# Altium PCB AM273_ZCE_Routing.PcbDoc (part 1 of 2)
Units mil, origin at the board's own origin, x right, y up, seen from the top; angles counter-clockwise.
Board outline 825 x 1150 mil, 4 copper layers (Top Layer, GND, Power, Bottom Layer), stack 60.63 mil thick; 37 components, 157 nets, 353 pads, 168 vias.
Unrouted connection lines stored in the file: 5.
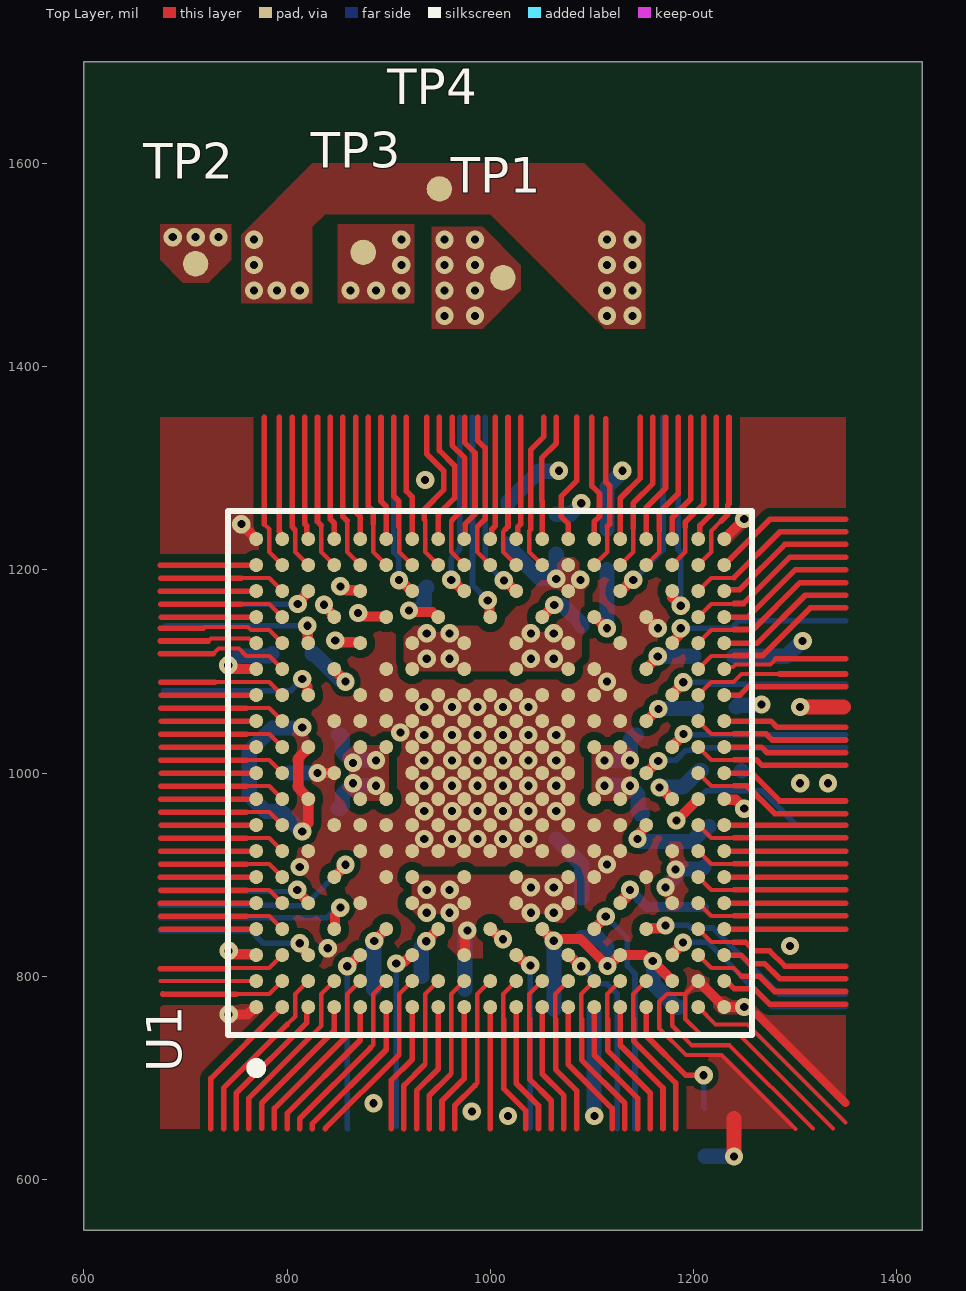
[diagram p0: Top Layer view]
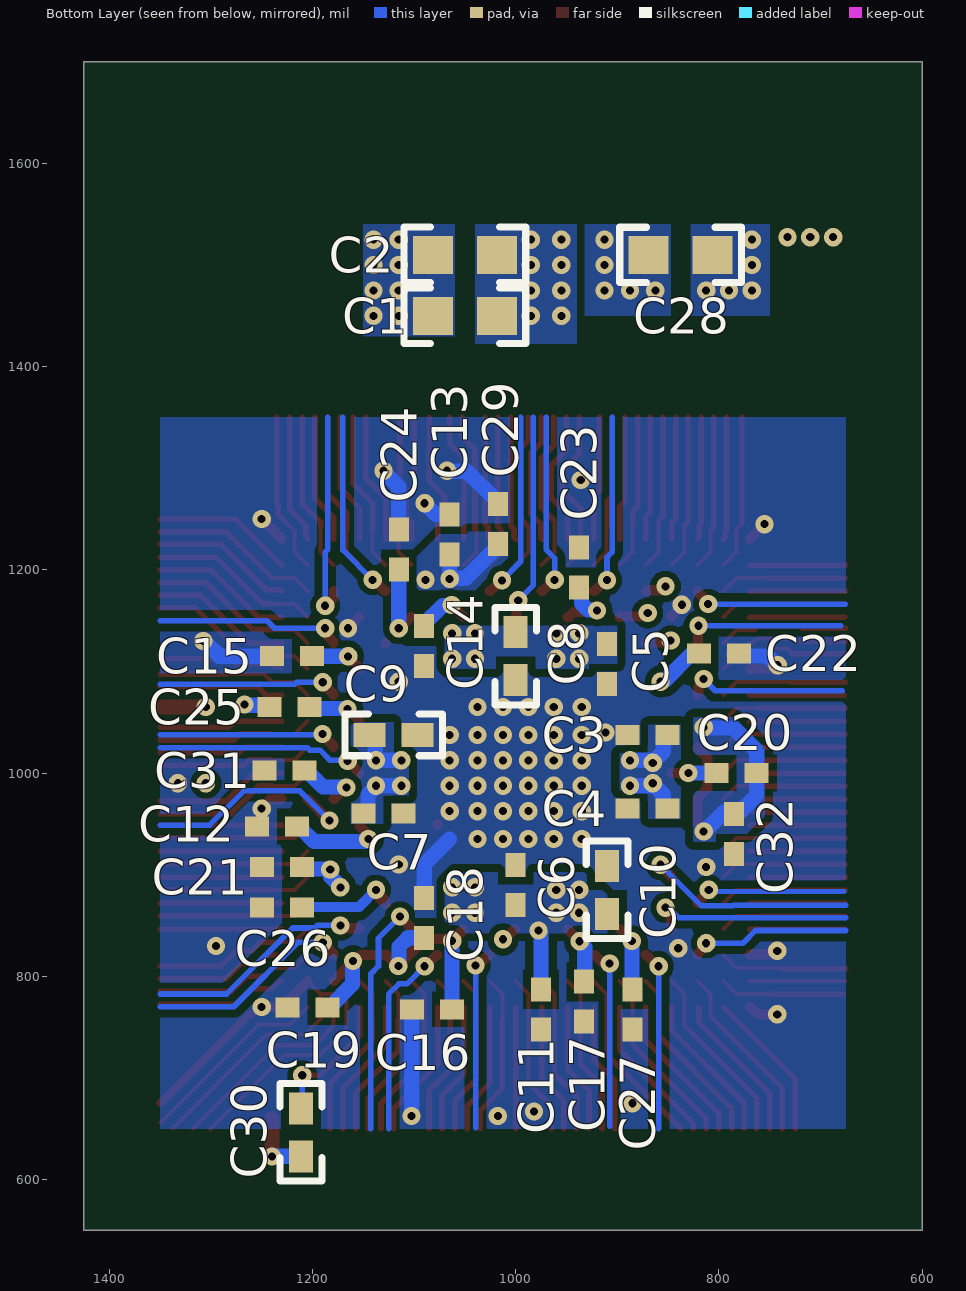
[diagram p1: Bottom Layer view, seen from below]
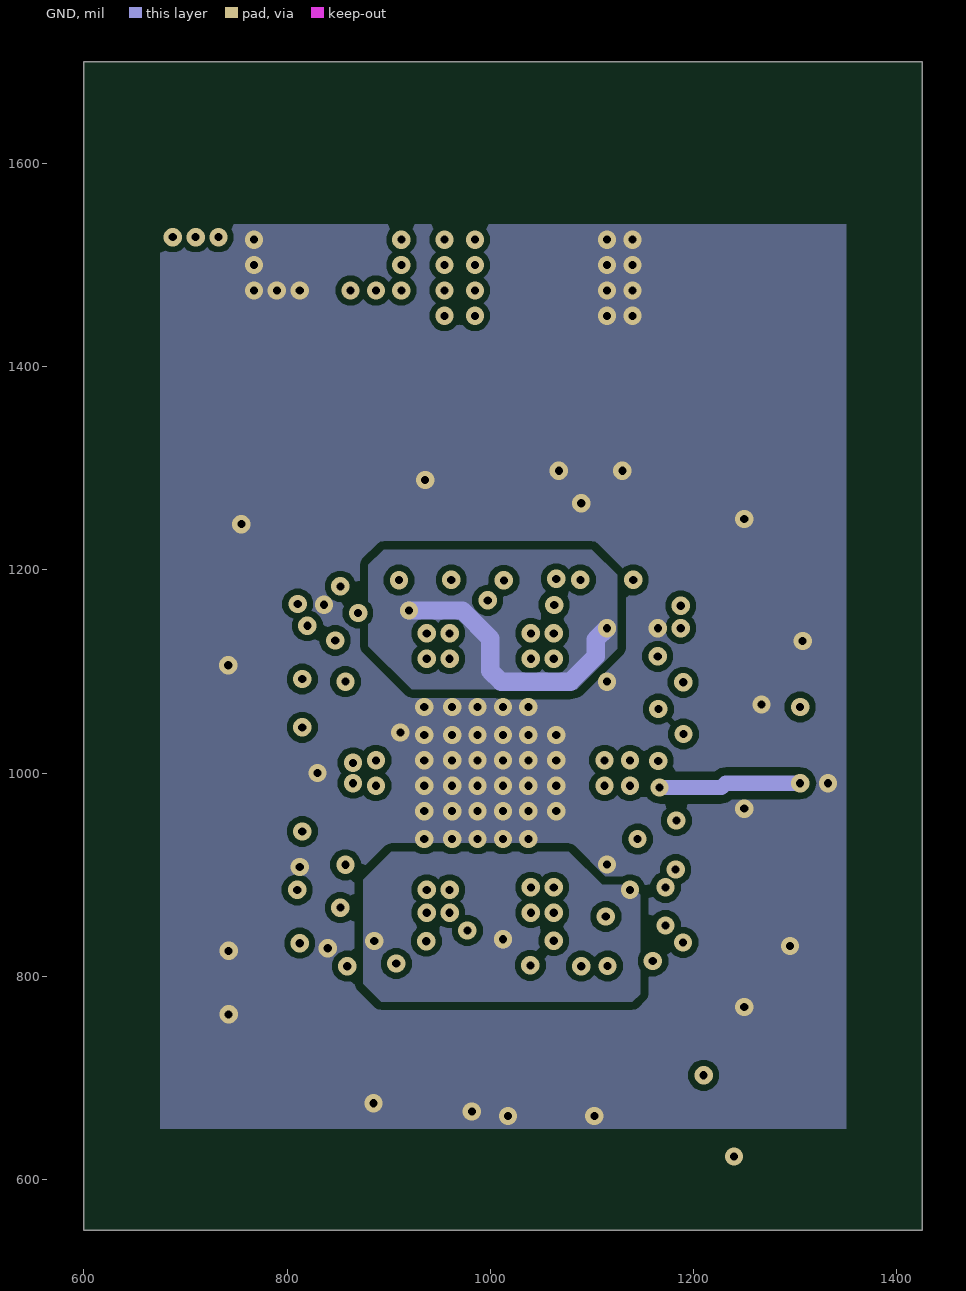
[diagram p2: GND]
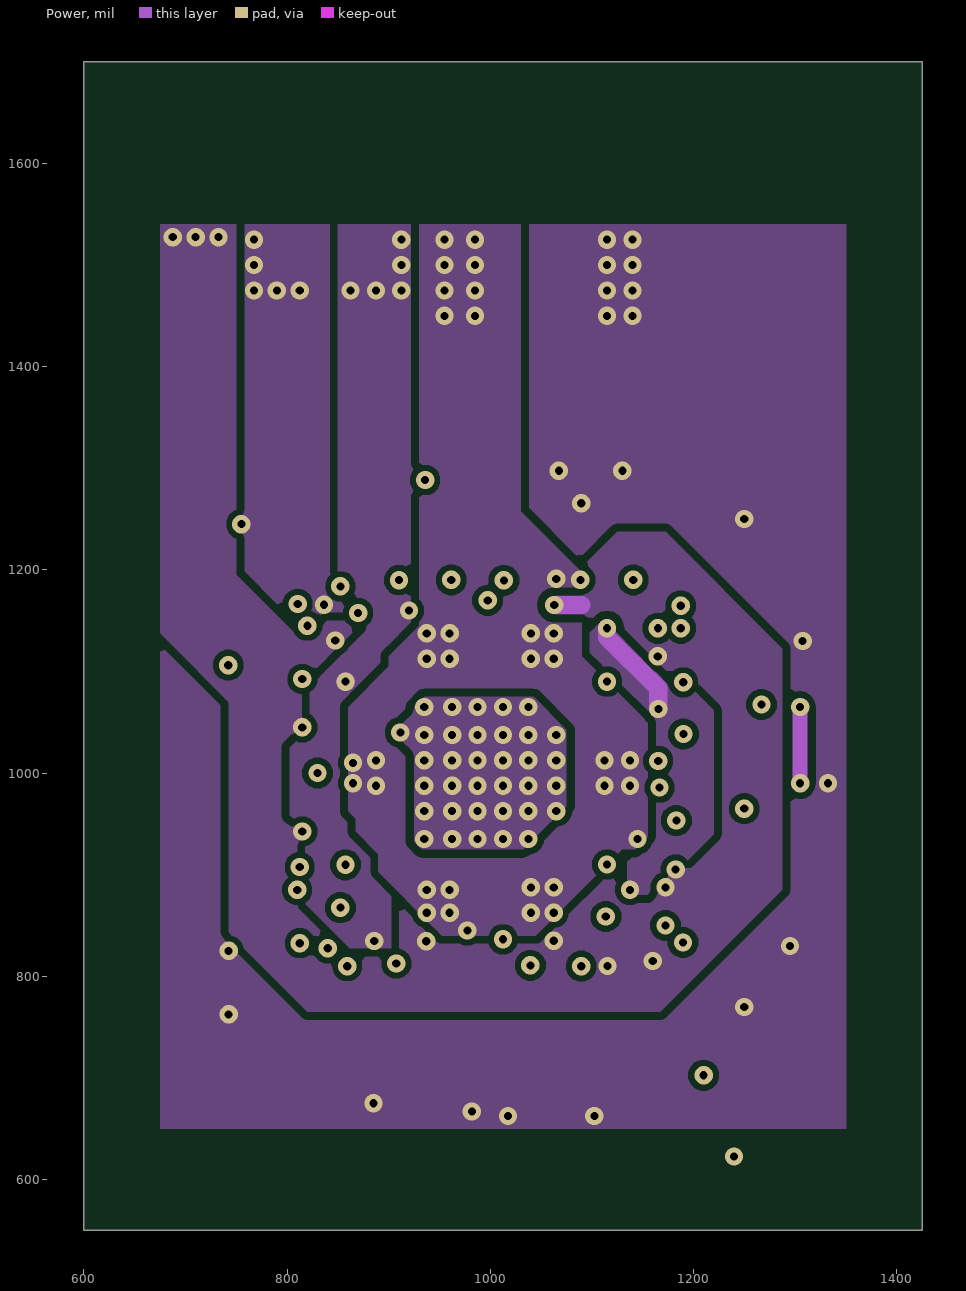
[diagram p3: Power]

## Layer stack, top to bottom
Top Solder: solder mask 0.394, Solder Resist, Dk 3.3
Top Layer: signal copper 1.378
Dielectric 1: prepreg 3.937, FR-4 High Tg, Dk 4.3
GND: signal copper 1.378
Dielectric 2: core 47.244, FR-4 High Tg, Dk 4.3
Power: signal copper 1.378
Dielectric 3: prepreg 3.937, FR-4 High Tg, Dk 4.3
Bottom Layer: signal copper 1.378
Bottom Solder: solder mask 0.394, Solder Resist, Dk 3.3

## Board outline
600,550 600,1700 1425,1700 1425,550

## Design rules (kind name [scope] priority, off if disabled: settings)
AcuteAngle [All] p1: minimum=4.50000000000000E+0001 checktracksonly=FALSE
AssemblyTestPointUsage [All] p1: valid=2
BoardOutlineClearance BoardOutlineClearance_MountingHoles [OnCopper and InComponentClass('Mounting Holes')] p1: gap=39.37 ignorepadtopadclearanceinfootprint=FALSE
BoardOutlineClearance BoardOutlineClearance_Poly [OnCopper and IsPoly] p2: gap=25 ignorepadtopadclearanceinfootprint=FALSE
BoardOutlineClearance [OnCopper and Not InComponentClass('Logo') and not InComponentClass('FiducialMark') and not InRegion(1000,500,4000,800) and not InPoly] p3: gap=40 ignorepadtopadclearanceinfootprint=FALSE
Clearance Clearance_Keepouts [((IsTrack Or IsArc) And Not InPoly) And IsFree and IsKeepOut vs ((IsTrack Or IsArc) And Not InPoly) And IsFree and IsKeepOut] p1: gap=0 ignorepadtopadclearanceinfootprint=FALSE
Clearance Clearance_Poly [InPolygon] p2: gap=10 ignorepadtopadclearanceinfootprint=TRUE except(6: Via-Fill Via-Poly Via-Region; 8: Arc-Fill Arc-Poly Arc-Region Track-Fill Track-Poly Track-Region SMDPad-Fill SMDPad-Poly SMDPad-Region Fill-Fill Fill-Poly Fill-Region Poly-Poly Poly-Region Region-Region; 12: THPad-Fill THPad-Poly THPad-Region)
Clearance Clearance_FiducialMark [IsKeepOut and InComponentClass('FiducialMark') vs IsPad and InComponentClass('FiducialMark')] p3: gap=0 ignorepadtopadclearanceinfootprint=FALSE
Clearance [All] p4: gap=4 ignorepadtopadclearanceinfootprint=TRUE except(3.52: SMDPad-Via; 3.9: Arc-SMDPad Track-SMDPad; 7.87: Arc-THPad Arc-Text Arc-Hole Track-THPad Track-Text Track-Hole SMDPad-THPad SMDPad-Text SMDPad-Hole THPad-THPad THPad-Via THPad-Fill THPad-Poly THPad-Region THPad-Text THPad-Hole Via-Text Via-Hole Fill-Text Fill-Hole Poly-Text Poly-Hole Region-Text Region-Hole Text-Text Text-Hole)
ComponentClearance ComponentClearance_MountingHoles_FiducialMarks [InComponentClass('Mounting Holes') vs InComponentClass('FiducialMark')] p1: gap=50 collisioncheckmode=3 verticalgap=10 showdistances=FALSE
ComponentClearance ComponentClearance_Shunt [InComponentClass('Header') vs InComponentClass('Shunt')] p2: gap=0 collisioncheckmode=3 verticalgap=0 showdistances=FALSE
ComponentClearance ComponentClearance_Logo [InComponentClass('Logo')] p3: gap=30 collisioncheckmode=3 verticalgap=10 showdistances=FALSE
ComponentClearance ComponentClearance_ScrewToNut [(HasFootprint('NY PMS 440 0025 PH')) vs (HasFootprint('Keystone_1902C'))] p4: gap=5 collisioncheckmode=3 verticalgap=10 showdistances=FALSE
ComponentClearance ComponentClearance_MountingHoles [InComponentClass('Mounting Holes')] p5: gap=100 collisioncheckmode=3 verticalgap=100000 showdistances=FALSE
ComponentClearance ComponentClearance_SmallPassives [HasFootprint('0201*') or HasFootprint('0402*') or HasFootprint('0508') or HasFootprint('0603*') or HasFootprint('0612') or HasFootprint('0805*') or HasFootprint('0815*') or HasFootprint('0830*') or HasFootprint('1206*') or HasFootprint('1210*') or HasFootprint('1808*') or HasFootprint('1812*') or HasFootprint('1825*') or HasFootprint('2010*') or HasFootprint('2220*') or HasFootprint('2225*') or HasFootprint('2512*') or HasFootprint('2728*') or HasFootprint('3518*') vs HasFootprint('0201*') or HasFootprint('0402*') or HasFootprint('0508') or HasFootprint('0603*') or HasFootprint('0612') or HasFootprint('0805*') or HasFootprint('0815*') or HasFootprint('0830*') or HasFootprint('1206*') or HasFootprint('1210*') or HasFootprint('1808*') or HasFootprint('1812*') or HasFootprint('1825*') or HasFootprint('2010*') or HasFootprint('2220*') or HasFootprint('2225*') or HasFootprint('2512*') or HasFootprint('2728*') or HasFootprint('3518*')] p6: gap=14.96 collisioncheckmode=3 verticalgap=10 showdistances=FALSE
ComponentClearance ComponentClearance_THtoSMT [IsThruComponent vs IsSMTComponent] p7: gap=30 collisioncheckmode=3 verticalgap=30 showdistances=FALSE
ComponentClearance ComponentClearance_THtoTH [IsThruComponent vs IsThruComponent] p8: gap=20 collisioncheckmode=3 verticalgap=30 showdistances=FALSE
ComponentClearance [All] p9: gap=20 collisioncheckmode=3 verticalgap=10 showdistances=FALSE
DiffPairsRouting [All] p1: maxlimit=100 minlimit=10 mostfreqgap=10 toplayer_minwidth=15 toplayer_maxwidth=15 toplayer_prefwidth=15 midlayer1_minwidth=15 midlayer1_maxwidth=15 midlayer1_prefwidth=15 midlayer4_minwidth=15 midlayer4_maxwidth=15 midlayer4_prefwidth=15 bottomlayer_minwidth=15 bottomlayer_maxwidth=15 bottomlayer_prefwidth=15 maxuncoupledlength=1000
FabricationTestPointUsage TestPointUsage [All] p1: valid=2 allowmultiple=FALSE
FabricationTestpoint Testpoint [All] p1: side=3 testpointundercomponent=TRUE minsize=40 maxsize=100 preferedsize=60 minholesize=0 maxholesize=40 preferedholesize=32 testpointgrid=1 allowsidetop=TRUE allowsidebottom=TRUE usegrid=TRUE gridtolerance=0.01
FanoutControl Fanout_LCC [IsLCC] p1: bgadir=Out bgaviamode=Centered fanoutstyle=Auto fanoutdirection=Alternating viagrid=1 // Fanout_LCC (Default Rule)
FanoutControl Fanout_BGA [IsBGA] p2: bgadir=Out bgaviamode=Centered fanoutstyle=Auto fanoutdirection=Alternating viagrid=1 // Fanout_BGA (Default Rule)
FanoutControl Fanout_Default [All] p4: bgadir=Out bgaviamode=Centered fanoutstyle=Auto fanoutdirection=Alternating viagrid=1 // Fanout_Default (Default Rule)
FanoutControl Fanout_Small [(CompPinCount < 5)] p5: bgadir=Out bgaviamode=Centered fanoutstyle=Auto fanoutdirection=OutThenIn viagrid=1 // Fanout_Small (Default Rule)
HoleSize [All] p1: absolutevalues=TRUE maxlimit=251 minlimit=7.87 maxpercent=80.000 minpercent=20.000
MinimumAnnularRing MinimumAnnularRing_ThermalPadVias [IsVia and InAnyComponent] p1: minimumring=5.91
MinimumAnnularRing [All] p2: minimumring=5
MinimumSolderMaskSliver MinimumSolderMaskSliver_Logo [InComponentClass('Logo') vs InComponentClass('Logo')] p1: minsoldermaskwidth=0.7
MinimumSolderMaskSliver [All] p2: minsoldermaskwidth=3.94
PlaneConnect [All] p1: planeconnectstyle=Relief reliefexpansion=10 reliefentries=4 reliefconductorwidth=10 reliefairgap=10
PolygonConnect [All] p1: connectstyle=Direct reliefconductorwidth=10 reliefentries=4 polygonreliefangle="90 Angle" airgapwidth=10
RoutingVias ThermalPadVias [IsVia and InAnyComponent] p1: holewidth=7.87 width=19.68 viastyle="Through Hole" minholewidth=7.87 minwidth=19.68 maxholewidth=12.99 maxwidth=23.62
RoutingVias [All] p2: holewidth=8 width=18 viastyle="Through Hole" minholewidth=8 minwidth=18 maxholewidth=40 maxwidth=65
SilkToBoardRegionClearance [Not ((IsComment or IsDesignator) And (Hide <> 'False')) and not InRegion(1000,500,4000,800)] p1:
SilkToSilkClearance SilkToSilkClearance_Pb-FreeLogo [(HasFootprint('Pb-Free_Overlay_Medium') OR HasFootprint('Pb-Free_Overlay_Small')) vs (HasFootprint('Pb-Free_Overlay_Medium') OR HasFootprint('Pb-Free_Overlay_Small'))] p1: silktosilkclearance=0
SilkToSilkClearance [All] p2: silktosilkclearance=3.94
SilkToSolderMaskClearance SilkToComponentPadClearance [(IsPad or IsFill or IsRegion) and InAnycomponent] p1: minsilkscreentomaskgap=5 clearancetoexposedcopper=TRUE
SilkToSolderMaskClearance "Silk to Solder Mask Opening" [All] p2: minsilkscreentomaskgap=3.94 clearancetoexposedcopper=FALSE
SolderMaskExpansion [All] p1: expansion=1.97 istentingtop=FALSE
UnRoutedNet [All] p1: checkbadconnections=TRUE
Width [All] p1: maxlimit=100 minlimit=4 preferedwidth=6 checkconnectedcopper=TRUE
14 further rules are at their usual default settings.

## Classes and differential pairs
component class AM273_ZCE_Device: TP1 TP2 TP3 TP4 U1
component class AM273_ZCE_Decoupling: C1 C2 C3 C4 C5 C6 C7 C8 C9 C10 C11 C12 C13 C14 C15 C16 C17 C18 C19 C20 C21 C22 C23 C24 C25 C26 C27 C28 C29 C30 C31 C32

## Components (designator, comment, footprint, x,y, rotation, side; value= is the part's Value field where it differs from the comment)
C1 "GCM188R70J225KE22D" 0603 1050,1450 r180 bottom value=2.2uF
C2 "GCM188R70J225KE22D" 0603 1050,1510 r180 bottom value=2.2uF
C3 "GCM155R71C224KE02D" 0402L 870,1037.5 r180 bottom value=0.22uF
C4 "GCM155R71C224KE02D" 0402L 870,965 r180 bottom value=0.22uF
C5 "GCM155R71C224KE02D" 0402L 910,1107.5 r90 bottom value=0.22uF
C6 "GCM155R71C224KE02D" 0402L 1000,890 r270 bottom value=0.22uF
C7 "GCM155R71C224KE02D" 0402L 1130,960 r0 bottom value=0.22uF
C8 "CGA2B3X7R1H103K050BB" 0402 1000,1115 r270 bottom value=0.01uF
C9 "CGA2B3X7R1H103K050BB" 0402 1120,1037.5 r180 bottom value=0.01uF
C10 "CGA2B3X7R1H103K050BB" 0402 910,885 r90 bottom value=0.01uF
C11 "GCM155R71C104KA55D" 0402L 975,767.5 r90 bottom value=0.1uF
C12 "GCM155R71C104KA55D" 0402L 1235,947.5 r180 bottom value=0.1uF
C13 "GCM155R71C224KE02D" 0402L 1065,1235 r270 bottom value=0.22uF
C14 "GCM155R71C224KE02D" 0402L 1090,1125 r90 bottom value=0.22uF
C15 "GCM155R71C224KE02D" 0402L 1220,1115 r180 bottom value=0.22uF
C16 "GCM155R71C224KE02D" 0402L 1082.5,767.5 r180 bottom value=0.22uF
C17 "GCM155R71C224KE02D" 0402L 932.5,775 r90 bottom value=0.22uF
C18 "GCM155R71C224KE02D" 0402L 1090,857.5 r270 bottom value=0.22uF
C19 "GCM155R71C224KE02D" 0402L 1205,769.41 r180 bottom value=0.22uF
C20 "GCM155R71C224KE02D" 0402L 782.5,1000 r180 bottom value=0.22uF
C21 "GCM155R71C224KE02D" 0402L 1230,907.5 r180 bottom value=0.22uF
C22 "GCM155R71C224KE02D" 0402L 800,1117.5 r0 bottom value=0.22uF
C23 "GCM155R71C224KE02D" 0402L 937.5,1202.5 r270 bottom value=0.22uF
C24 "GCM155R71C224KE02D" 0402L 1115,1220 r270 bottom value=0.22uF
C25 "GCM155R71C224KE02D" 0402L 1222.5,1065 r180 bottom value=0.22uF
C26 "GCM155R71C224KE02D" 0402L 1230,867.5 r180 bottom value=0.22uF
C27 "GCM155R71C224KE02D" 0402L 885,767.5 r90 bottom value=0.22uF
C28 "GCM188R70J225KE22D" 0603 837.5,1510 r0 bottom value=2.2uF
C29 "GCM155R71C104KA55D" 0402L 1017.5,1245 r270 bottom value=0.1uF
C30 "CGA2B3X7R1H473K050BB" 0402 1211.28,646.38 r270 bottom value=0.047uF
C31 "GCM155R71C104KA55D" 0402L 1227.5,1002.5 r180 bottom value=0.1uF
C32 "GCM155R71C224KE02D" 0402L 785,940 r90 bottom value=0.22uF
TP1 "TESTPOINT" TP_25MIL-SMT 1012.5,1487.5 r0 top
TP2 "TESTPOINT" TP_25MIL-SMT 710,1501.25 r0 top
TP3 "TESTPOINT" TP_25MIL-SMT 875,1512.5 r0 top
TP4 "TESTPOINT" TP_25MIL-SMT 950,1575 r0 top
U1 "AM2732ADRFGAZCER" ZCE0285A-MFG 1000,1000 r90 top

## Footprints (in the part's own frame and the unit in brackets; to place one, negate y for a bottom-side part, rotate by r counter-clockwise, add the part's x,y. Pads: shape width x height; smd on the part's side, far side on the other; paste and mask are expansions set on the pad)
0402 [mm] "0402 from SM-752 data"
  rect 0.8x0.6 smd: 1(-0.6,0) 2(0.6,0)
  silkscreen extent -1.22,-0.52 1.22,0.52, body extent -0.55,-0.3 0.55,0.3, height 0.6
0402L [mm] "0402 from SM-752 data"
  rect 0.6x0.5 smd: 1(-0.5,0) 2(0.5,0)
  body extent -0.55,-0.3 0.55,0.3, height 0.6
0603 [mm] "0603 from SM-752 data"
  rect 1x0.95 smd: 1(-0.8,0) 2(0.8,0)
  silkscreen extent -1.52,-0.69 1.52,0.69, body extent -0.87,-0.47 0.87,0.47, height 1
TP_25MIL-SMT [mil]
  round 25 smd mask-2.5: 1(0,0)
ZCE0285A-MFG [mm]
  round 0.35 smd paste+0 mask-1000: A1(-5.85,5.85) A2(-5.2,5.85) A3(-4.55,5.85) A4(-3.9,5.85) A5(-3.25,5.85) A6(-2.6,5.85) A7(-1.95,5.85) A8(-1.3,5.85) A9(-0.65,5.85) A10(0,5.85) A11(0.65,5.85) A12(1.3,5.85) A13(1.95,5.85) A14(2.6,5.85) A15(3.25,5.85) A16(3.9,5.85) A17(4.55,5.85) A18(5.2,5.85) A19(5.85,5.85) B1(-5.85,5.2) B2(-5.2,5.2) B3(-4.55,5.2) B4(-3.9,5.2) B5(-3.25,5.2) B6(-2.6,5.2) B7(-1.95,5.2) B8(-1.3,5.2) B9(-0.65,5.2) B10(0,5.2) B11(0.65,5.2) B12(1.3,5.2) B13(1.95,5.2) B14(2.6,5.2) B15(3.25,5.2) B16(3.9,5.2) B17(4.55,5.2) B18(5.2,5.2) B19(5.85,5.2) C1(-5.85,4.55) C2(-5.2,4.55) C3(-4.55,4.55) C5(-3.25,4.55) C7(-1.95,4.55) C9(-0.65,4.55) C11(0.65,4.55) C13(1.95,4.55) C15(3.25,4.55) C17(4.55,4.55) C18(5.2,4.55) C19(5.85,4.55) D1(-5.85,3.9) D2(-5.2,3.9) D4(-3.9,3.9) D6(-2.6,3.9) D8(-1.3,3.9) D10(0,3.9) D12(1.3,3.9) D14(2.6,3.9) D16(3.9,3.9) D18(5.2,3.9) D19(5.85,3.9) E1(-5.85,3.25) E2(-5.2,3.25) E3(-4.55,3.25) E5(-3.25,3.25) E7(-1.95,3.25) E8(-1.3,3.25) E9(-0.65,3.25) E11(0.65,3.25) E12(1.3,3.25) E13(1.95,3.25) E15(3.25,3.25) E17(4.55,3.25) E18(5.2,3.25) E19(5.85,3.25) F1(-5.85,2.6) F2(-5.2,2.6) F4(-3.9,2.6) F6(-2.6,2.6) F7(-1.95,2.6) F8(-1.3,2.6) F9(-0.65,2.6) F11(0.65,2.6) F12(1.3,2.6) F13(1.95,2.6) F14(2.6,2.6) F16(3.9,2.6) F18(5.2,2.6) F19(5.85,2.6) G1(-5.85,1.95) G2(-5.2,1.95) G3(-4.55,1.95) G5(-3.25,1.95) G6(-2.6,1.95) G7(-1.95,1.95) G8(-1.3,1.95) G9(-0.65,1.95) G10(0,1.95) G11(0.65,1.95) G12(1.3,1.95) G13(1.95,1.95) G14(2.6,1.95) G15(3.25,1.95) G17(4.55,1.95) G18(5.2,1.95) G19(5.85,1.95) H1(-5.85,1.3) H2(-5.2,1.3) H4(-3.9,1.3) H7(-1.95,1.3) H8(-1.3,1.3) H9(-0.65,1.3) H10(0,1.3) H11(0.65,1.3) H12(1.3,1.3) H13(1.95,1.3) H16(3.9,1.3) H18(5.2,1.3) H19(5.85,1.3) J1(-5.85,0.65) J2(-5.2,0.65) J3(-4.55,0.65) J5(-3.25,0.65) J6(-2.6,0.65) J7(-1.95,0.65) J8(-1.3,0.65) J9(-0.65,0.65) J10(0,0.65) J11(0.65,0.65) J12(1.3,0.65) J13(1.95,0.65) J14(2.6,0.65) J15(3.25,0.65) J17(4.55,0.65) J18(5.2,0.65) J19(5.85,0.65) K1(-5.85,0) K2(-5.2,0) K4(-3.9,0) K7(-1.95,0) K8(-1.3,0) K9(-0.65,0) K10(0,0) K11(0.65,0) K12(1.3,0) K13(1.95,0) K16(3.9,0) K18(5.2,0) K19(5.85,0) L1(-5.85,-0.65) L2(-5.2,-0.65) L3(-4.55,-0.65) L5(-3.25,-0.65) L6(-2.6,-0.65) L7(-1.95,-0.65) L8(-1.3,-0.65) L9(-0.65,-0.65) L10(0,-0.65) L11(0.65,-0.65) L12(1.3,-0.65) L13(1.95,-0.65) L14(2.6,-0.65) L15(3.25,-0.65) L17(4.55,-0.65) L18(5.2,-0.65) L19(5.85,-0.65) M1(-5.85,-1.3) M2(-5.2,-1.3) M4(-3.9,-1.3) M7(-1.95,-1.3) M8(-1.3,-1.3) M9(-0.65,-1.3) M10(0,-1.3) M11(0.65,-1.3) M12(1.3,-1.3) M13(1.95,-1.3) M16(3.9,-1.3) M18(5.2,-1.3) M19(5.85,-1.3) N1(-5.85,-1.95) N2(-5.2,-1.95) N3(-4.55,-1.95) N5(-3.25,-1.95) N6(-2.6,-1.95) N7(-1.95,-1.95) N8(-1.3,-1.95) N9(-0.65,-1.95) N10(0,-1.95) N11(0.65,-1.95) N12(1.3,-1.95) N13(1.95,-1.95) N14(2.6,-1.95) N15(3.25,-1.95) N17(4.55,-1.95) N18(5.2,-1.95) N19(5.85,-1.95) P1(-5.85,-2.6) P2(-5.2,-2.6) P4(-3.9,-2.6) P6(-2.6,-2.6) P7(-1.95,-2.6) P8(-1.3,-2.6) P9(-0.65,-2.6) P11(0.65,-2.6) P12(1.3,-2.6) P13(1.95,-2.6) P14(2.6,-2.6) P16(3.9,-2.6) P18(5.2,-2.6) P19(5.85,-2.6) R1(-5.85,-3.25) R2(-5.2,-3.25) R3(-4.55,-3.25) R5(-3.25,-3.25) R7(-1.95,-3.25) R8(-1.3,-3.25) R9(-0.65,-3.25) R11(0.65,-3.25) R12(1.3,-3.25) R13(1.95,-3.25) R15(3.25,-3.25) R17(4.55,-3.25) R18(5.2,-3.25) R19(5.85,-3.25) T1(-5.85,-3.9) T2(-5.2,-3.9) T4(-3.9,-3.9) T6(-2.6,-3.9) T8(-1.3,-3.9) T10(0,-3.9) T12(1.3,-3.9) T14(2.6,-3.9) T16(3.9,-3.9) T18(5.2,-3.9) T19(5.85,-3.9) U1(-5.85,-4.55) U2(-5.2,-4.55) U3(-4.55,-4.55) U5(-3.25,-4.55) U7(-1.95,-4.55) U9(-0.65,-4.55) U11(0.65,-4.55) U13(1.95,-4.55) U15(3.25,-4.55) U17(4.55,-4.55) U18(5.2,-4.55) U19(5.85,-4.55) V1(-5.85,-5.2) V2(-5.2,-5.2) V3(-4.55,-5.2) V4(-3.9,-5.2) V5(-3.25,-5.2) V6(-2.6,-5.2) V7(-1.95,-5.2) V8(-1.3,-5.2) V9(-0.65,-5.2) V10(0,-5.2) V11(0.65,-5.2) V12(1.3,-5.2) V13(1.95,-5.2) V14(2.6,-5.2) V15(3.25,-5.2) V16(3.9,-5.2) V17(4.55,-5.2) V18(5.2,-5.2) V19(5.85,-5.2) W1(-5.85,-5.85) W2(-5.2,-5.85) W3(-4.55,-5.85) W4(-3.9,-5.85) W5(-3.25,-5.85) W6(-2.6,-5.85) W7(-1.95,-5.85) W8(-1.3,-5.85) W9(-0.65,-5.85) W10(0,-5.85) W11(0.65,-5.85) W12(1.3,-5.85) W13(1.95,-5.85) W14(2.6,-5.85) W15(3.25,-5.85) W16(3.9,-5.85) W17(4.55,-5.85) W18(5.2,-5.85) W19(5.85,-5.85)
  silkscreen extent -7.5,-6.55 6.55,6.55, body extent -7.05,-7.05 7.05,7.05, height 0.25

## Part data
C1 C2 C28: library part CMP-0007134-5, "CAP, CERM, 2.2 uF, 6.3 V, +/- 10%, X7R, AEC-Q200 Grade 1, 0603", Cap_Case=0603, Manufacturer=MuRata, Supplier Part Number 1=490-5316-1-ND, TempCo=X7R, Tolerance_%=10%, Value1=Unknown, Value2=6.3V, ValueDisplayed=2.2uF
C3 C4 C5 C6 C7 C13 C14 C15 C16 C17 C18 C19 C20 C21 C22 C23 C24 C25 C26 C27 C32: library part CMP-0078265-1, "CAP, CERM, 0.22 µF, 16 V,+/- 10%, X7R, AEC-Q200 Grade 1, 0402", Cap_Case=0402, Manufacturer=MuRata, Supplier Part Number 1=490-10671-1-ND, TempCo=X7R, Tolerance_%=10%, Value2=16V, ValueDisplayed=0.22µF
C8 C9 C10: library part CMP-0006324-2, "CAP, CERM, 0.01 uF, 50 V, +/- 10%, X7R, AEC-Q200 Grade 1, 0402", Cap_Case=0402, Manufacturer=TDK, Supplier Part Number 1=445-6893-1-ND, TempCo=X7R, Tolerance_%=10%, Value1="0.333065 ohm", Value2=50V, ValueDisplayed=0.01uF
C11 C12 C29 C31: library part CMP-0006351-2, "CAP, CERM, 0.1 uF, 16 V, +/- 10%, X7R, 0402", Cap_Case=0402, Manufacturer=MuRata, Supplier Part Number 1=490-4759-2-ND, TempCo=X7R, Tolerance_%=10%, Value1=Unknown, Value2=16V, ValueDisplayed=0.1uF
C30: library part CMP-0006330-2, "CAP, CERM, 0.047 uF, 50 V, +/- 10%, X7R, AEC-Q200 Grade 1, 0402", Cap_Case=0402, Manufacturer=TDK, Supplier Part Number 1=445-6897-1-ND, TempCo=X7R, Tolerance_%=10%, Value1="0.06407 ohm", Value2=50V, ValueDisplayed=0.047uF
TP1 TP2 TP3 TP4: library part CMP-0078143-3, "TEST POINT.  No entry in BOM.", Manufacturer=N/A
U1: library part CMP-0094014-2, "Radar Controller and Processor", Frequency_Fixed=400MHz, Manufacturer="Texas Instruments", Max Supply Voltage=3.465V, Min Supply Voltage=1.14V, Operating Temperature Range="-40°C to +105°C"

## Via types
v1: diameter 18, hole 8, Top Layer to Bottom Layer, tented both sides, 168 vias

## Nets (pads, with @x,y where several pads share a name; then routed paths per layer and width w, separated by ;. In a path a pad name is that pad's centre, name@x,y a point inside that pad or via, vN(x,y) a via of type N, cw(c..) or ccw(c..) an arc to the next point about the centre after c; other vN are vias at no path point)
1V2_VDD: C1.2 C2.2 C3.2 C4.2 C5.2 C6.2 C7.2 C8.1 C9.1 C10.1 C11.2 C12.2 C13.2 C29.2 TP1.1 U1.E9 U1.E11 U1.F9 U1.F11 U1.G5 U1.G6 U1.G14 U1.G15 U1.J3 U1.J5 U1.J6 U1.J14 U1.J15 U1.L5 U1.L6 U1.L14 U1.L15 U1.N5 U1.N6 U1.N14 U1.N15 U1.N17 U1.N18 U1.P9 U1.P11 U1.R9 U1.R11 U1.T8 | length 488.7
  Top Layer w10: U1.J3@974.84,820.43 U1.J3@974.41,820.87 975.13,821.59 975.13,840.47 977.5,842.84 v1(977.5,845) ; v1(1145,935) 1146.53,936.53 1146.53,940.78 1153.54,947.8 U1.T8@1153.54,948.82
  Bottom Layer w15: C4.2@850.31,965 852.28,965 854.63,967.34 854.63,978.81 862.5,986.69 862.5,987.5 v1(887.5,987.5) ; C3.2@850.31,1037.5 852.28,1037.5 854.63,1035.16 854.63,1021.19 862.5,1013.31 862.5,1012.5 v1(887.5,1012.5) ; C11.2@975,787.19 975,841.69 977.5,844.19 v1(977.5,845) ; C29.2@1017.5,1225.31 1017.5,1223.35 1049.17,1191.68 1064.43,1191.68 v1(1065,1191.1) C13.2@1065,1215.31 ; v1(1112.5,987.5) v1(1137.5,987.5) 1137.5,986.69 1145.37,978.81 1145.37,962.34 1147.72,960 C7.2@1149.69,960 ; v1(1112.5,1012.5) v1(1137.5,1012.5) 1138.07,1013.07 1138.07,1033.19 1142.38,1037.5 C9.1@1143.62,1037.5 ; v1(1145,935) 1145.81,935 1148.31,932.5 1198.35,932.5 1211,945.16 1212.97,945.16 C12.2@1215.31,947.5
  other v1: 937.5,862.5 960,862.5 1040,862.5 1062.5,862.5 937.5,885 960,885 1040,887.5 1062.5,887.5 865,990 865,1010 937.5,1112.5 960,1112.5 1040,1112.5 1062.5,1112.5 937.5,1137.5 960,1137.5 1040,1137.5 1062.5,1137.5 1088.67,1190.14 955,1450 985,1450 955,1475 985,1475 955,1500 985,1500 955,1525 985,1525
1V7_VPP: C31.2 U1.U9 | length 323
  Top Layer w10: v1(1166.65,985.69) 1167.25,985.69 1178.54,974.41 U1.U9@1179.13,974.41
  Top Layer w15: v1(1305,1065) 1347.5,1065
  Power w15: v1(1305,989.91) v1(1305,1065)
  GND w15: v1(1166.65,985.69) 1227.5,985.69 1231.71,989.91 v1(1305,989.91)
  Bottom Layer w15: v1(1166.65,985.69) 1167.23,986.27 1189.62,986.27 1205.85,1002.5 C31.2@1207.81,1002.5
1V8_AM273: C14.2 C15.2 C16.2 C17.2 C18.2 C19.2 C20.2 C21.2 C32.2 TP2.1 U1.C9 U1.C11 U1.E15 U1.H4 U1.M4 U1.M16 U1.R3 U1.T14 U1.U2 U1.U5 U1.U7 | length 861.1
  Top Layer w10: v1(815,942.5) 815,944.66 820.87,950.53 U1.C9@820.87,974.41 820.87,975.43 811.07,985.23 811.07,1014.77 820.87,1024.57 U1.C11@820.87,1025.59 ; v1(847.43,1130.51) 849.6,1130.51 851.43,1128.68 871.32,1128.68 U1.E15@872.05,1127.95 ; v1(937.03,834.51) 937.03,834.59 948.82,846.38 U1.H4@948.82,846.46 ; U1.M4@1051.18,846.46 1051.18,846.39 1062.5,835.07 v1(1062.5,835) 1064.66,835 1066.33,836.66 1088.89,836.66 v1(1115.44,810.11) 1116.32,810.11 U1.R3@1127.51,821.3 ; U1.M16@1051.18,1153.54 1051.18,1153.62 1062.97,1165.41 v1(1062.97,1165.49) ; U1.R3@1127.95,820.87 1151.97,820.87 1157.84,815 v1(1160,815) 1160,814.7 1179.13,795.57 U1.U2@1179.13,795.28 ; U1.T14@1153.54,1102.36 1153.54,1102.96 1164.83,1114.24 v1(1164.83,1114.84)
  Power w18: v1(1062.97,1165.49) 1089.51,1165.49
  Bottom Layer w15: v1(815,942.5) 814.19,942.5 794.5,962.19 778.71,962.19 762.81,978.09 C20.2@762.81,1000 762.81,1021.6 785.64,1044.43 814.43,1044.43 v1(815,1045) ; C17.2@932.5,799.69 932,800.19 932,828.66 937.03,833.69 v1(937.03,834.51) ; v1(1062.5,835) 1062.66,834.84 1062.66,767.66 C16.2@1062.81,767.5 ; v1(1062.97,1165.49) 1063.54,1164.92 1071.73,1164.92 1090,1146.65 C14.2@1090,1144.69 ; C18.2@1090,837.81 1106.08,837.81 1114.87,829.03 1114.87,810.68 v1(1115.44,810.11) ; v1(1160,815) 1160.57,814.43 1160.57,792.18 1183.35,769.41 C19.2@1185.31,769.41 ; v1(1164.83,1114.84) 1164.91,1114.92 1200.24,1114.92 C15.2@1200.31,1115 ; v1(1172.5,887.5) 1172.5,888.31 1181.93,897.74 1181.93,904.43 v1(1182.5,905) 1183.07,905.57 1208.39,905.57 C21.2@1210.31,907.5
  other v1: 687.5,1527.5 710,1527.5 732.5,1527.5
3V3_AM273: C22.2 C23.2 C24.2 C25.2 C26.2 C27.2 C28.2 TP3.1 U1.D14 U1.F4 U1.H16 U1.K4 U1.P16 U1.R5 U1.T12 | length 811.7
  Top Layer w10: U1.D14@846.46,1102.36 846.46,1101.7 857.5,1090.66 v1(857.5,1090) ; v1(885.77,834.59) U1.F4@897.64,846.46 ; v1(920,1160) 921.53,1158.47 942.87,1158.47 947.8,1153.54 U1.H16@948.82,1153.54 ; U1.K4@1000,846.46 1001.02,846.46 1011.1,836.38 v1(1012.53,836.38) ; U1.P16@1102.36,1153.54 1103.16,1153.54 1114.2,1142.5 v1(1115,1142.5) ; U1.T12@1153.54,1051.18 1153.62,1051.18 1165.41,1062.97 v1(1165.49,1062.97)
  Top Layer w12: U1.R5@1127.95,872.05 1127.95,872.53 1136.35,880.93 1136.35,883.85 v1(1137.5,885)
  Power w18: v1(857.5,1090) v1@858.11,1090 ; v1(1115,1142.5) 1115,1133.56 1165.49,1083.06 v1(1165.49,1062.97)
  GND w18: v1(920,1160) 972.5,1160 1000,1132.5 1000,1100.54 1010.54,1090 1078.94,1090 1103.78,1114.84 1103.78,1131.28 v1(1115,1142.5)
  Bottom Layer w10: v1(1137.5,885) 1154.5,868 1209.81,868 C26.2@1210.31,867.5
  Bottom Layer w15: C22.2@824.69,1117.5 826.65,1117.5 853.58,1090.57 856.93,1090.57 v1(857.5,1090) ; C27.2@885,787.19 885.38,787.57 885.38,834.2 v1(885.77,834.59) ; v1(920,1160) 920.57,1160.57 928.71,1160.57 935.16,1167.02 935.16,1180.47 C23.2@937.5,1182.81 ; v1@1012.53,835.56 v1(1012.53,836.38) ; v1(1115,1142.5) C24.2@1115,1200.31 ; v1(1165.49,1062.97) 1166.07,1063.54 1201.36,1063.54 C25.2@1202.81,1065
  other v1: 862.5,1475 887.5,1475 912.5,1475 912.5,1500 912.5,1525
ADC1: U1.R2 | length 168.1
  Top Layer w4: 1115.45,757.5 1115.16,757.79 1115.16,782.48 U1.R2@1127.95,795.28
  Top Layer w5.5: 1115.45,757.5 1115.45,727.05 1157.5,685 1157.5,650
ADC2: U1.P2 | length 168.4
  Top Layer w4: 1089.86,757.5 1089.57,757.79 1089.57,782.48 U1.P2@1102.36,795.28
  Top Layer w5.5: 1089.86,757.5 1089.86,717.64 1132.5,675 1132.5,650
ADC3: U1.R1 | length 137.1
  Top Layer w5.5: U1.R1@1127.95,769.68 1127.95,732.05 1170,690 1170,650
ADC4: U1.P1 | length 137.3
  Top Layer w5.5: U1.P1@1102.36,769.68 1102.36,722.64 1145,680 1145,650
ADC5: U1.M2 | length 159.5
  Top Layer w4: 1038.68,757.5 1038.39,757.79 1038.39,782.48 U1.M2@1051.18,795.28
  Top Layer w5.5: 1038.68,757.5 1038.68,698.82 1060,677.5 1060,650
ADC6: U1.T2 | length 167.9
  Top Layer w4: 1141.04,757.5 1140.75,757.79 1140.75,782.48 U1.T2@1153.54,795.28
  Top Layer w5.5: 1141.04,757.5 1141.04,736.46 1182.5,695 1182.5,650
ADC7: U1.N2 | length 159.3
  Top Layer w4: 1064.27,757.5 1063.98,757.79 1063.98,782.48 U1.N2@1076.77,795.28
  Top Layer w5.5: 1064.27,757.5 1064.27,708.23 1085,687.5 1085,650
ADC8: U1.N1 | length 137.6
  Top Layer w5.5: U1.N1@1076.77,769.68 1076.77,713.23 1120,670 1120,650
ADC9: U1.M1 | length 128.5
  Top Layer w5.5: U1.M1@1051.18,769.68 1051.18,703.82 1072.5,682.5 1072.5,650
CLKM: U1.U1 | length 198.7
  Top Layer w4: U1.U1@1179.13,769.68 1179.13,751.28 1198.35,732.07 1235.43,732.07 1317.5,650
CLKP: U1.V1 | length 192.1
  Top Layer w4: U1.V1@1204.72,769.68 1221.91,752.5 1253.27,752.5 1349.72,656.04
CSI2_RX0CLKM: U1.B6 | length 124.8
  Top Layer w4: 759.84,910.43 782.48,910.43 U1.B6@795.28,897.64
  Top Layer w5.5: 675.75,910.43 759.84,910.43
CSI2_RX0CLKP: U1.A6 | length 94.5
  Top Layer w5.5: 675.14,897.64 U1.A6@769.68,897.64
CSI2_RX0M0: U1.A8 | length 93.5
  Top Layer w5.5: 676.18,948.82 U1.A8@769.68,948.82
CSI2_RX0M1: U1.A7 | length 94
  Top Layer w5.5: 675.73,923.23 U1.A7@769.68,923.23
CSI2_RX0M2: U1.B5 | length 124.8
  Top Layer w4: 759.84,884.84 782.48,884.84 U1.B5@795.28,872.05
  Top Layer w5.5: 675.75,884.84 759.84,884.84
CSI2_RX0M3: U1.B4 | length 124.8
  Top Layer w4: 759.84,859.25 782.48,859.25 U1.B4@795.28,846.46
  Top Layer w5.5: 675.75,859.25 759.84,859.25
CSI2_RX0P0: U1.B8 | length 124.8
  Top Layer w4: 759.84,961.61 782.48,961.61 U1.B8@795.28,948.82
  Top Layer w5.5: 675.75,961.61 759.84,961.61
CSI2_RX0P1: U1.B7 | length 124.8
  Top Layer w4: 759.84,936.02 782.48,936.02 U1.B7@795.28,923.23
  Top Layer w5.5: 675.75,936.02 759.84,936.02
CSI2_RX0P2: U1.A5 | length 94.2
  Top Layer w5.5: 675.45,872.05 U1.A5@769.68,872.05
CSI2_RX0P3: U1.A4 | length 93.2
  Top Layer w5.5: 676.46,846.46 U1.A4@769.68,846.46
CSI2_RX1CLKM: U1.A11 | length 93.2
  Top Layer w5.5: 676.46,1025.59 U1.A11@769.68,1025.59
CSI2_RX1CLKP: U1.B11 | length 124.8
  Top Layer w4: 760,1038.39 782.48,1038.39 U1.B11@795.28,1025.59
  Top Layer w5.5: 675.75,1038.39 760,1038.39
CSI2_RX1M0: U1.A13 | length 93.2
  Top Layer w5.5: 676.46,1076.77 U1.A13@769.68,1076.77
CSI2_RX1M1: U1.B12 | length 124.8
  Top Layer w4: 760,1063.98 782.48,1063.98 U1.B12@795.28,1051.18
  Top Layer w5.5: 675.75,1063.98 760,1063.98
CSI2_RX1M2: U1.A10 | length 93.2
  Top Layer w5.5: 676.46,1000 U1.A10@769.68,1000
CSI2_RX1M3: U1.A9 | length 94.1
  Top Layer w5.5: 675.59,974.41 U1.A9@769.68,974.41
CSI2_RX1P0: U1.B13 | length 124.8
  Top Layer w4: 729.11,1089.57 782.48,1089.57 U1.B13@795.28,1076.77
  Top Layer w5.5: 675.75,1089.57 729.11,1089.57
CSI2_RX1P1: U1.A12 | length 93.2
  Top Layer w5.5: 676.46,1051.18 U1.A12@769.68,1051.18
CSI2_RX1P2: U1.B10 | length 124.8
  Top Layer w4: 760,1012.79 782.48,1012.79 U1.B10@795.28,1000
  Top Layer w5.5: 675.75,1012.79 760,1012.79
CSI2_RX1P3: U1.B9 | length 124.8
  Top Layer w4: 760,987.2 782.48,987.2 U1.B9@795.28,974.41
  Top Layer w5.5: 675.75,987.2 760,987.2
DSS_UARTA_RX: U1.H19 | length 132.6
  Top Layer w5.5: U1.H19@948.82,1230.32 948.82,1254.42 965,1270.6 965,1302.5 950,1317.5 950,1350
DSS_UARTA_TX: U1.J19 | length 128.2
  Top Layer w5.5: U1.J19@974.41,1230.32 975.45,1231.36 975.45,1245.45 985,1255 985,1315 975,1325 975,1350
E\R\R\O\R\_\I\N\: U1.L3 | length 178
  Top Layer w10: U1.L3@1025.59,820.87 1026.61,820.87 1035.22,812.26 1037.92,812.26 v1(1039.45,810.73)
  Bottom Layer w5.5: 1039.45,650.76 v1(1039.45,810.73)
E\R\R\O\R\_\O\U\T\: U1.L1 | length 128.8
  Top Layer w5.5: U1.L1@1025.59,769.68 1025.59,694.41 1047.5,672.5 1047.5,650
E\R\R\O\R\I\N\_\F\E\1\: U1.C15 | length 157.4
  Top Layer w10: v1(820,1145) 820.43,1144.57 820.43,1128.39 U1.C15@820.87,1127.95
  Bottom Layer w5.5: 680,1145 v1(820,1145)
E\R\R\O\R\I\N\_\F\E\2\: U1.A16 | length 93.6
  Top Layer w5.5: 676.04,1153.54 U1.A16@769.68,1153.54
FE1_REFCLK: U1.H1 | length 128.5
  Top Layer w5.5: 927.5,650 927.5,687.5 948.82,708.82 U1.H1@948.82,769.68
FE2_REFCLK: U1.J2 | length 159.5
  Top Layer w4: 960,702.5 961.61,704.11 961.61,782.48 U1.J2@974.41,795.28
  Top Layer w5.5: 940,650 940,682.5 960,702.5
GND: C1.1 C2.1 C3.1 C4.1 C5.1 C6.1 C7.1 C8.2 C9.2 C10.2 C11.1 C12.1 C13.1 C14.1 C15.1 C16.1 C17.1 C18.1 C19.1 C20.1 C21.1 C22.1 C23.1 C24.1 C25.1 C26.1 C27.1 C28.1 C29.1 C30.2 C31.1 C32.1 TP4.1 U1.A1 U1.A3 U1.A14 U1.A19 U1.C7 U1.D8 U1.D10 U1.D12 U1.D16 U1.E5 U1.E7 U1.E8 U1.E12 U1.E13 U1.F6 U1.F7 U1.F8 U1.F12 U1.F13 U1.F14 U1.G7 U1.G8 U1.G9 U1.G10 U1.G11 U1.G12 U1.G13 U1.H7 U1.H8 U1.H9 U1.H10 U1.H11 U1.H12 U1.H13 U1.J7 U1.J8 U1.J9 U1.J10 U1.J11 U1.J12 U1.J13 U1.K7 U1.K8 U1.K9 U1.K10 U1.K11 U1.K12 U1.K13 U1.L7 U1.L8 U1.L9 U1.L10 U1.L11 U1.L12 U1.L13 U1.M7 U1.M8 U1.M9 U1.M10 U1.M11 U1.M12 U1.M13 U1.N7 U1.N8 U1.N9 U1.N10 U1.N11 U1.N12 U1.N13 U1.P6 U1.P7 U1.P8 U1.P12 U1.P13 U1.P14 U1.R7 U1.R8 U1.R12 U1.R13 U1.R15 U1.T6 U1.T16 U1.V2 U1.W1 U1.W9 U1.W19 | length 1441.7
  Top Layer w4: U1.V2@1204.72,795.28 1191.93,782.48 ; 1300.31,649.69 1227.5,722.5 1192.5,722.5 1166.34,748.66 1166.34,774.98 1173.84,782.48 1191.93,782.48 ; 1337.5,650 1245,742.5 1207.5,742.5 1191.93,758.07 1191.93,782.48
  Top Layer w8: v1(1250,769.68) 1252.71,769.68 1259.89,762.5 1262.5,762.5 1349.72,675.28
  Top Layer w10: v1(742.13,1106.12) 745.88,1102.36 U1.A14@769.68,1102.36 ; v1(742.5,762.5) 761.48,762.5 768.66,769.68 U1.A1@769.68,769.68 ; v1(742.5,825) 744.66,825 748.08,821.59 768.96,821.59 U1.A3@769.68,820.87 ; v1(755,1245) U1.A19@769.68,1230.32 ; v1(830,1000) U1.D10@846.46,1000 ; v1(836.38,1165.66) 836.38,1164.64 846.46,1154.56 U1.D16@846.46,1153.54 ; U1.N8@1076.77,948.82 U1.N8@1076.77,949.84 ; U1.R15@1127.95,1127.48 U1.R15@1127.95,1127.95 ; U1.T16@1153.54,1153.54 1153.75,1153.54 1164.79,1142.5 v1(1165,1142.5) ; U1.V2@1204.72,795.28 U1.W1@1230.32,769.68 v1(1250,769.68) ; U1.W9@1230.32,974.41 1231.04,973.69 1241.65,973.69 1247.84,967.5 v1@1250,967.5 ; U1.W19@1230.32,1230.32 v1(1250,1250)
  Top Layer w15: v1(1239.85,622.5) 1239.85,659.85 1240,660
  Bottom Layer w15: v1(742.13,1106.12) 742.94,1106.12 751.98,1115.16 782.97,1115.16 C22.1@785.32,1117.5 ; C20.1@802.18,1000 v1(830,1000) ; C29.1@1017.5,1264.68 1017.5,1266.65 1047.77,1296.93 1066.93,1296.93 v1(1067.5,1297.5) ; 1065,935 1090,910 C18.1@1090,877.18 ; C13.1@1065,1254.68 1078.74,1254.68 v1(1089.57,1265.51) ; C16.1@1102.18,767.5 1102.18,662.82 v1(1102.5,662.5) ; C24.1@1115,1239.68 1115,1281.69 1130,1296.69 v1(1130,1297.5) ; C30.2@1211.28,622.76 1239.6,622.76 v1(1239.85,622.5) ; C15.1@1239.68,1115 1291.69,1115 1306.69,1130 v1(1307.5,1130) ; C25.1@1242.18,1065 1244,1066.82 1266.34,1066.82 v1(1266.91,1067.39) ; C31.1@1247.18,1002.5 C31.1@1247.77,1001.91 ; v1@1249.43,964.43 v1(1250,965) ; v1@1332.41,989.91 v1(1332.5,990)
  other v1: 1017.5,662.5 981.89,666.89 885,675 840,827.5 1295,829.72 812.5,907.5 1115,910 935,935 962.5,935 987.5,935 1012.5,935 1037.5,935 935,962.5 962.5,962.5 987.5,962.5 1012.5,962.5 1037.5,962.5 1065,962.5 935,987.5 962.5,987.5 987.5,987.5 1012.5,987.5 1037.5,987.5 1065,987.5 935,1012.5 962.5,1012.5 987.5,1012.5 1012.5,1012.5 1037.5,1012.5 1065,1012.5 935,1037.5 962.5,1037.5 987.5,1037.5 1012.5,1037.5 1037.5,1037.5 1065,1037.5 911.5,1040 935,1065 962.5,1065 987.5,1065 1012.5,1065 1037.5,1065 1115,1090 935.94,1288.33 1115,1450 1140,1450 767.5,1475 790,1475 812.5,1475 1115,1475 1140,1475 767.5,1500 1115,1500 1140,1500 767.5,1525 1115,1525 1140,1525
HW_SYNC_FE1: U1.V17 | length 169.5
  Top Layer w4: U1.V17@1204.72,1179.13 1217.52,1191.93 1239.43,1191.93 1240,1192.5
  Top Layer w5.5: 1240,1192.5 1285,1237.5 1350,1237.5
HW_SYNC_FE2: U1.W17 | length 138.4
  Top Layer w5.5: U1.W17@1230.32,1179.13 1231.64,1180.45 1245.45,1180.45 1290,1225 1349.72,1225
LVDS_CLKM: U1.W7 | length 119.7
  Top Layer w5.5: U1.W7@1230.32,923.23 1350,923.23
LVDS_CLKP: U1.V7 | length 150.7
  Top Layer w4: U1.V7@1204.72,923.23 1217.52,910.43 1239.71,910.43 1240,910.73
  Top Layer w5.5: 1240,910.73 1350,910.73
LVDS_FRCLKM: U1.W8 | length 119.7
  Top Layer w5.5: U1.W8@1230.32,948.82 1350,948.82
LVDS_FRCLKP: U1.V8 | length 150.7
  Top Layer w4: U1.V8@1204.72,948.82 1217.52,936.02 1239.71,936.02 1240,936.32
  Top Layer w5.5: 1240,936.32 1350,936.32
LVDS_TXM0: U1.V6 | length 150.7
  Top Layer w4: U1.V6@1204.72,897.64 1217.52,884.84 1239.71,884.84 1240,885.14
  Top Layer w5.5: 1240,885.14 1350,885.14
LVDS_TXM1: U1.V5 | length 150.7
  Top Layer w4: U1.V5@1204.72,872.05 1217.52,859.25 1239.71,859.25 1240,859.55
  Top Layer w5.5: 1240,859.55 1350,859.55
LVDS_TXM2: U1.V4 | length 160.4
  Top Layer w4: U1.V4@1204.72,846.46 1217.52,833.66 1239.71,833.66
  Top Layer w5.5: 1239.71,833.66 1251.34,833.66 1260,825 1275,825 1290,810 1350,810
LVDS_TXM3: U1.V3 | length 160.1
  Top Layer w4: U1.V3@1204.72,820.87 1217.52,808.07 1239.43,808.07 1247.5,800
  Top Layer w5.5: 1247.5,800 1265,800 1280,785 1350,785
LVDS_TXP0: U1.W6 | length 119.7
  Top Layer w5.5: U1.W6@1230.32,897.64 1350,897.64
LVDS_TXP1: U1.W5 | length 119.7
  Top Layer w5.5: U1.W5@1230.32,872.05 1350,872.05
LVDS_TXP2: U1.W4 | length 119.7
  Top Layer w5.5: U1.W4@1230.32,846.46 1350,846.46
LVDS_TXP3: U1.W3 | length 129.4
  Top Layer w5.5: U1.W3@1230.32,820.87 1246.63,820.87 1255,812.5 1270,812.5 1285,797.5 1350,797.5
MSS_EPWMA0: U1.E3 | length 177.3
  Top Layer w10: v1(859.25,809.86) 860.15,809.86 871.15,820.87 U1.E3@872.05,820.87
  Bottom Layer w5.5: v1(859.25,809.86) 859.25,650.3 859.55,650
MSS_GPIO_2: U1.H2 | length 159.3
  Top Layer w4: 935,712.5 936.02,713.52 936.02,782.48 U1.H2@948.82,795.28
  Top Layer w5.5: 915,650 915,692.5 935,712.5
MSS_GPIO_8: U1.B3 | length 125.8
  Top Layer w4: 737.5,807.5 738.07,808.07 782.48,808.07 U1.B3@795.28,820.87
  Top Layer w5.5: 675,807.5 737.5,807.5
MSS_GPIO_9: U1.B19 | length 120.8
  Top Layer w5.5: 792.5,1350 792.5,1237.5 793.69,1236.31 793.69,1231.9 U1.B19@795.28,1230.32
MSS_GPIO_10: U1.B18 | length 152.6
  Top Layer w4: 777.5,1245 782.48,1240.02 782.48,1217.52 U1.B18@795.28,1204.72
  Top Layer w5.5: 777.5,1245 777.5,1350
MSS_GPIO_11: U1.C17 | length 151.8
  Top Layer w10: v1(810.5,1166.34) 810.5,1167.75 820.87,1178.11 U1.C17@820.87,1179.13
  Bottom Layer w5.5: 675.75,1166.34 v1(810.5,1166.34)
MSS_GPIO_12: U1.A18 | length 94.4
  Top Layer w5.5: 675.28,1204.72 U1.A18@769.68,1204.72
MSS_GPIO_13: U1.B17 | length 124.8
  Top Layer w4: 755,1191.93 782.48,1191.93 U1.B17@795.28,1179.13
  Top Layer w5.5: 675.75,1191.93 755,1191.93
MSS_GPIO_28: U1.G3 | length 179.2
  Top Layer w10: v1(907.5,812.5) 909.03,814.03 915.37,814.03 922.21,820.87 U1.G3@923.23,820.87
  Bottom Layer w5.5: 907.5,652.5 v1(907.5,812.5)
MSS_I2CA_SCL: U1.F18 | length 152.6
  Top Layer w4: 884.84,1245.45 884.84,1217.52 U1.F18@897.64,1204.72
  Top Layer w5.5: 880,1350 880,1262.5 884.84,1257.66 884.84,1245.45
MSS_I2CA_SDA: U1.F16 | length 29.6
  Top Layer w10: v1(870,1157.5) 872.16,1157.5 875.75,1153.92 896.57,1153.92 896.91,1154.27 U1.F16@897.64,1153.54
MSS_MCANA_RX: U1.B2 | length 123.1
  Top Layer w4: 750,782.48 782.48,782.48 U1.B2@795.28,795.28
  Top Layer w5.5: 677.52,782.48 750,782.48
MSS_MCANA_TX: U1.A2 | length 94.4
  Top Layer w4: 675.28,795.28 U1.A2@769.68,795.28
MSS_MCANB_RX: U1.C1 | length 149
  Top Layer w5.5: 750,650 750,685 819.55,754.55 819.55,768.36 U1.C1@820.87,769.68
MSS_MCANB_TX: U1.B1 | length 148.8
  Top Layer w5.5: 725,650 725,699.41 U1.B1@795.28,769.68
MSS_MDIO_CLK: U1.R19 | length 127.8
  Top Layer w5.5: U1.R19@1127.95,1230.32 1127.95,1270.45 1147.5,1290 1147.5,1350
MSS_MDIO_DATA: U1.P19 | length 124.9
  Top Layer w5.5: 1100,1350 1100,1282.5 1107.5,1275 1107.5,1252.6 1102.36,1247.46 U1.P19@1102.36,1230.32
MSS_MIBSPIA_CLK: U1.G19 | length 122.1
  Top Layer w5.5: 917.5,1350 917.5,1277.5 923.23,1271.77 U1.G19@923.23,1230.32
MSS_MIBSPIA_CS0: U1.F19 | length 121.8
  Top Layer w5.5: 892.5,1350 892.5,1267.5 897.64,1262.36 U1.F19@897.64,1230.32
MSS_MIBSPIA_HOSTIRQ: U1.G18 | length 152.8
  Top Layer w4: 910,1242.5 910.43,1242.07 910.43,1217.52 U1.G18@923.23,1204.72
  Top Layer w5.5: 905,1350 905,1272.5 910,1267.5 910,1242.5
MSS_MIBSPIA_MISO: U1.G17 | length 179.8
  Top Layer w10: v1(910.12,1189.86) 911.48,1189.86 922.21,1179.13 U1.G17@923.23,1179.13
  Bottom Layer w5.5: 905,1350 905,1217.5 910.12,1212.39 v1(910.12,1189.86)
MSS_MIBSPIA_MOSI: U1.H18 | length 165.8
  Top Layer w4: 935,1250 936.02,1248.98 936.02,1217.52 U1.H18@948.82,1204.72
  Top Layer w5.5: 935,1250 935,1259.59 954.15,1278.74 954.15,1297.5 937.5,1314.15 937.5,1350
MSS_MIBSPIB_CLK: U1.D18 | length 152.1
  Top Layer w4: 833.66,1243.84 833.66,1217.52 U1.D18@846.46,1204.72
  Top Layer w5.5: 830,1350 830,1247.5 833.66,1243.84
MSS_MIBSPIB_CS0: U1.D19 | length 121.3
  Top Layer w5.5: 842.5,1350 842.5,1250 846.46,1246.04 U1.D19@846.46,1230.32
MSS_MIBSPIB_CS1: U1.E18 | length 152.3
  Top Layer w4: 859.25,1248.25 859.25,1217.52 U1.E18@872.05,1204.72
  Top Layer w5.5: 855,1350 855,1252.5 859.25,1248.25
MSS_MIBSPIB_CS2: U1.E17 | length 21.5
  Top Layer w10: v1(852.5,1183.75) 854.66,1183.75 858.56,1179.86 871.32,1179.86 U1.E17@872.05,1179.13
MSS_MIBSPIB_MISO: U1.C19 | length 121.1
  Top Layer w5.5: 817.5,1350 817.5,1245 819.28,1243.22 819.28,1231.9 U1.C19@820.87,1230.32
MSS_MIBSPIB_MOSI: U1.C18 | length 151.8
  Top Layer w4: 807.5,1240 808.07,1239.43 808.07,1217.52 U1.C18@820.87,1204.72
  Top Layer w5.5: 805,1350 805,1242.5 807.5,1240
